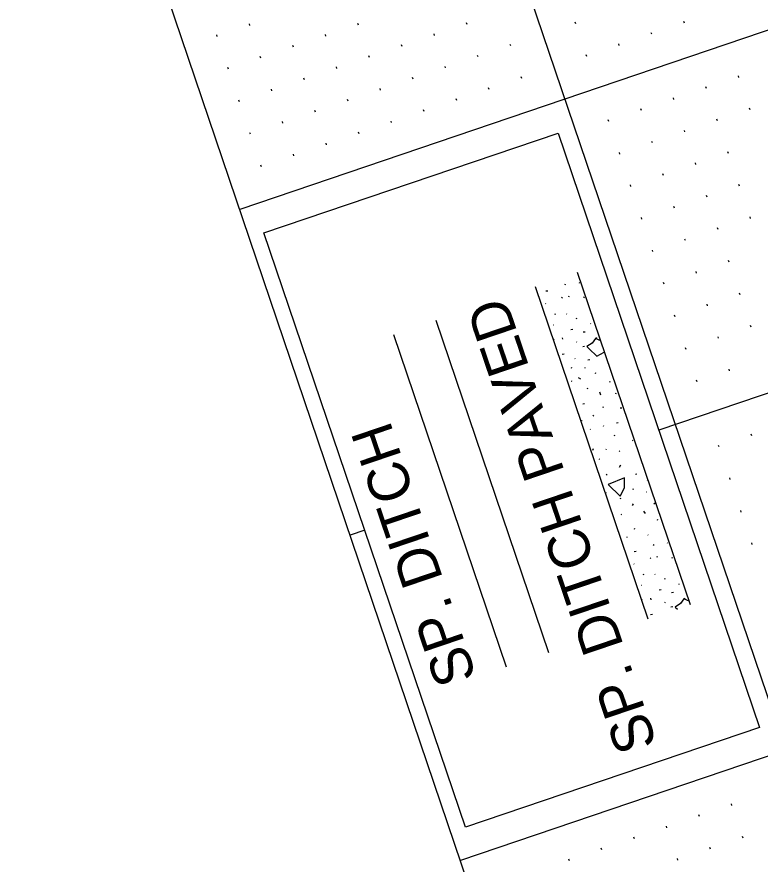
# Model space of a CAD drawing. Extents: x 2150318 to 2152065, y 143281 to 145371.
# Drawn here: x 2150992.2 to 2151100.4, y 144672.2 to 144795.4 of the extents above; entities that cross this region are included whole.
import ezdxf

# ---------------------------------------------------------------- set-up
doc = ezdxf.new("R2010")
doc.units = 0
for name, color, linetype in [('PR_Grading_Txt', 7, 'Continuous'), ('PR_Misc_Improvement', 7, 'Continuous'), ('PR_Storm_Ditch_Paved', 7, 'Continuous'), ('PR_Storm_Ditch_Special', 7, 'Continuous'), ('SHT_Profile_Grid_Major', 7, 'Continuous'), ('SHT_Profile_Grid_Minor', 7, 'Continuous'), ('SHT_Sheet_Border', 7, 'Continuous')]:
    doc.layers.add(name, color=color, linetype=linetype)

msp = doc.modelspace()

# ---------------------------------------------------------------- linework, layer by layer
at = {"layer": 'PR_Misc_Improvement'}
msp.add_lwpolyline([(2151057.47, 144677.53), (2151028.14, 144763.99), (2151070.97, 144778.52), (2151100.3, 144692.06)], close=True, dxfattribs=at)
at = {"layer": 'PR_Storm_Ditch_Paved'}
for p, q in [((2151072.08, 144756.42), (2151071.94, 144756.49)), ((2151073.99, 144756.77), (2151074.06, 144756.74)), ((2151069.2, 144755.55), (2151069.47, 144755.59)), ((2151071.52, 144754.49), (2151071.59, 144754.63)), ((2151072.61, 144754.69), (2151072.47, 144754.76)), ((2151074.79, 144754.56), (2151074.65, 144754.63)), ((2151069.12, 144753.73), (2151069.19, 144753.7)), ((2151070.65, 144752.12), (2151070.51, 144752.18)), ((2151072.18, 144752.23), (2151072.24, 144752.2)), ((2151073.75, 144751.49), (2151073.61, 144751.56)), ((2151075.7, 144752.56), (2151075.74, 144752.56)), ((2151070.23, 144750.64), (2151070.3, 144750.61)), ((2151075.66, 144750.81), (2151075.73, 144750.78)), ((2151072.83, 144749.97), (2151073.1, 144750)), ((2151074.63, 144749.59), (2151074.9, 144749.63)), ((2151070.4, 144748.45), (2151070.26, 144748.52)), ((2151071.64, 144748.52), (2151071.62, 144748.75)), ((2151073.62, 144748.15), (2151073.69, 144748.12)), ((2151076.52, 144748.62), (2151076.59, 144748.76)), ((2151074.54, 144747.48), (2151074.81, 144747.52)), ((2151071.57, 144746.36), (2151071.84, 144746.4)), ((2151073.4, 144745.72), (2151073.47, 144745.68)), ((2151075.31, 144745.55), (2151075.58, 144745.59)), ((2151073.01, 144744.31), (2151072.87, 144744.38)), ((2151074.83, 144744.41), (2151074.9, 144744.37)), ((2151073.87, 144742.98), (2151074.23, 144742.76)), ((2151076.51, 144743.53), (2151076.37, 144743.6)), ((2151072.88, 144742.48), (2151072.95, 144742.44)), ((2151078.49, 144742.3), (2151078.56, 144742.44)), ((2151075.24, 144741.31), (2151075.31, 144741.45)), ((2151077.01, 144740.87), (2151077.15, 144740.46)), ((2151079.37, 144740.57), (2151079.43, 144740.71)), ((2151074.54, 144739.11), (2151074.8, 144739.2)), ((2151077.61, 144738.59), (2151077.47, 144738.66)), ((2151080.15, 144738.41), (2151080.14, 144738.64)), ((2151074.4, 144736.64), (2151074.47, 144736.78)), ((2151076.18, 144737.35), (2151076.04, 144737.42)), ((2151077.55, 144735.86), (2151077.62, 144736)), ((2151079.46, 144736.38), (2151079.73, 144736.42)), ((2151075.62, 144735.43), (2151075.69, 144735.4)), ((2151079.17, 144734.5), (2151079.24, 144734.64)), ((2151081.91, 144733.75), (2151081.77, 144733.82)), ((2151076.02, 144732.39), (2151076.1, 144732.65)), ((2151077.94, 144732.5), (2151077.99, 144732.57)), ((2151079.95, 144732.22), (2151079.86, 144732.3)), ((2151076.91, 144731.13), (2151076.98, 144731.09)), ((2151080.04, 144730.23), (2151079.87, 144729.88)), ((2151078.11, 144728.76), (2151077.97, 144728.83)), ((2151082.23, 144728.89), (2151082.44, 144728.96)), ((2151083.98, 144727.98), (2151084.04, 144728.09)), ((2151077.9, 144726.15), (2151077.97, 144726.29)), ((2151082, 144726.67), (2151081.86, 144726.74)), ((2151083.79, 144726.35), (2151083.85, 144726.32)), ((2151080.03, 144725.31), (2151080.1, 144725.45)), ((2151081.8, 144724.35), (2151081.96, 144724.58)), ((2151084.9, 144724.59), (2151085.09, 144724.72)), ((2151083.7, 144723.2), (2151083.42, 144723.51)), ((2151080.1, 144723.08), (2151080.17, 144723.05)), ((2151085.54, 144722.21), (2151085.4, 144722.28)), ((2151082.17, 144720.89), (2151082.03, 144720.96)), ((2151080.93, 144719.78), (2151081, 144719.75)), ((2151084.01, 144720.07), (2151084.08, 144720.04)), ((2151084.93, 144718.54), (2151084.79, 144718.61)), ((2151086.84, 144718.89), (2151086.91, 144718.86)), ((2151082.05, 144717.67), (2151082.32, 144717.71)), ((2151081.97, 144715.86), (2151082.04, 144715.82)), ((2151084.37, 144716.61), (2151084.44, 144716.75)), ((2151085.46, 144716.81), (2151085.32, 144716.88)), ((2151087.64, 144716.68), (2151087.5, 144716.75)), ((2151088.55, 144714.68), (2151088.59, 144714.68)), ((2151083.5, 144714.24), (2151083.36, 144714.31)), ((2151085.03, 144714.35), (2151085.09, 144714.32)), ((2151086.6, 144713.61), (2151086.46, 144713.68)), ((2151083.08, 144712.76), (2151083.15, 144712.73)), ((2151085.68, 144712.09), (2151085.95, 144712.12)), ((2151088.51, 144712.93), (2151088.58, 144712.9)), ((2151084.49, 144710.64), (2151084.47, 144710.87)), ((2151087.48, 144711.71), (2151087.75, 144711.75)), ((2151089.37, 144710.74), (2151089.44, 144710.88)), ((2151083.25, 144710.57), (2151083.11, 144710.64)), ((2151086.47, 144710.27), (2151086.54, 144710.24)), ((2151087.39, 144709.6), (2151087.66, 144709.64)), ((2151084.42, 144708.48), (2151084.69, 144708.52))]:
    msp.add_line(p, q, dxfattribs=at)
for points in [[(2151077.18, 144748.29), (2151076.43, 144748.65), (2151075.93, 144747.98), (2151075.16, 144747.45), (2151075.5, 144747.12)], [(2151075.5, 144747.12), (2151076.61, 144746.05), (2151077.68, 144746.67), (2151077.7, 144746.77)], [(2151080.61, 144728.37), (2151078.23, 144727.38), (2151080.01, 144725.71), (2151080.63, 144726.89), (2151080.63, 144728.36)], [(2151090.03, 144710.41), (2151089.28, 144710.77), (2151088.78, 144710.1), (2151088.01, 144709.57), (2151088.35, 144709.24)]]:
    msp.add_lwpolyline(points, dxfattribs=at)
at = {"layer": 'PR_Storm_Ditch_Special'}
for p, q in [((2151090.22, 144709.88), (2151073.81, 144758.24)), ((2151084.07, 144707.79), (2151067.66, 144756.16)), ((2151069.62, 144702.89), (2151053.21, 144751.26)), ((2151063.47, 144700.8), (2151047.07, 144749.17))]:
    msp.add_line(p, q, dxfattribs=at)
at = {"layer": 'SHT_Profile_Grid_Major'}
for p, q in [((2151453.47, 143658.9), (2150947.48, 145150.41)), ((2151498.11, 144928.02), (2151024.62, 144767.39)), ((2151514.18, 144880.67), (2151085.63, 144735.29)), ((2151530.24, 144833.32), (2151056.74, 144672.69)), ((2151042.81, 144720.76), (2151040.68, 144720.04))]:
    msp.add_line(p, q, dxfattribs=at)
at = {"layer": 'SHT_Profile_Grid_Minor'}
for p, q in [((2151073.53, 144794.41), (2151073.45, 144794.65)), ((2151089.34, 144794.49), (2151089.26, 144794.73)), ((2151026.1, 144794.16), (2151026.02, 144794.4)), ((2151041.91, 144794.24), (2151041.83, 144794.48)), ((2151057.72, 144794.33), (2151057.64, 144794.56)), ((2151021.36, 144792.55), (2151021.28, 144792.79)), ((2151037.17, 144792.64), (2151037.09, 144792.87)), ((2151052.98, 144792.72), (2151052.9, 144792.96)), ((2151084.61, 144792.89), (2151084.53, 144793.12)), ((2151032.44, 144791.03), (2151032.36, 144791.27)), ((2151048.25, 144791.11), (2151048.17, 144791.35)), ((2151064.06, 144791.2), (2151063.98, 144791.43)), ((2151079.87, 144791.28), (2151079.79, 144791.52)), ((2151043.51, 144789.51), (2151043.43, 144789.74)), ((2151059.33, 144789.59), (2151059.25, 144789.83)), ((2151075.14, 144789.68), (2151075.06, 144789.91)), ((2151027.7, 144789.42), (2151027.62, 144789.66)), ((2151022.97, 144787.82), (2151022.89, 144788.05)), ((2151038.78, 144787.9), (2151038.7, 144788.14)), ((2151054.59, 144787.99), (2151054.51, 144788.22)), ((2151034.04, 144786.29), (2151033.96, 144786.53)), ((2151049.86, 144786.38), (2151049.78, 144786.62)), ((2151065.67, 144786.46), (2151065.59, 144786.7)), ((2151097.29, 144786.63), (2151097.21, 144786.87)), ((2151029.31, 144784.69), (2151029.23, 144784.93)), ((2151045.12, 144784.77), (2151045.04, 144785.01)), ((2151060.93, 144784.86), (2151060.85, 144785.09)), ((2151092.55, 144785.02), (2151092.47, 144785.26)), ((2151087.82, 144783.42), (2151087.74, 144783.65)), ((2151024.57, 144783.08), (2151024.49, 144783.32)), ((2151040.39, 144783.17), (2151040.31, 144783.4)), ((2151056.2, 144783.25), (2151056.12, 144783.49)), ((2151035.65, 144781.56), (2151035.57, 144781.8)), ((2151051.46, 144781.64), (2151051.38, 144781.88)), ((2151083.08, 144781.81), (2151083, 144782.05)), ((2151098.9, 144781.9), (2151098.82, 144782.13)), ((2151030.92, 144779.95), (2151030.84, 144780.19)), ((2151046.73, 144780.04), (2151046.65, 144780.27)), ((2151078.35, 144780.21), (2151078.27, 144780.44)), ((2151094.16, 144780.29), (2151094.08, 144780.53)), ((2151041.99, 144778.43), (2151041.91, 144778.67)), ((2151089.43, 144778.68), (2151089.35, 144778.92)), ((2151026.18, 144778.35), (2151026.1, 144778.58)), ((2151037.26, 144776.82), (2151037.18, 144777.06)), ((2151084.69, 144777.08), (2151084.61, 144777.31)), ((2151032.52, 144775.22), (2151032.44, 144775.46)), ((2151079.96, 144775.47), (2151079.88, 144775.71)), ((2151095.77, 144775.55), (2151095.69, 144775.79)), ((2151027.79, 144773.61), (2151027.71, 144773.85)), ((2151091.03, 144773.95), (2151090.95, 144774.18)), ((2151086.3, 144772.34), (2151086.22, 144772.58)), ((2151081.56, 144770.74), (2151081.48, 144770.97)), ((2151097.37, 144770.82), (2151097.29, 144771.06)), ((2151092.64, 144769.21), (2151092.56, 144769.45)), ((2151087.9, 144767.61), (2151087.82, 144767.84)), ((2151098.98, 144766.08), (2151098.9, 144766.32)), ((2151083.17, 144766), (2151083.09, 144766.24)), ((2151094.24, 144764.48), (2151094.16, 144764.72)), ((2151089.51, 144762.87), (2151089.43, 144763.11)), ((2151084.77, 144761.27), (2151084.69, 144761.5)), ((2151095.85, 144759.74), (2151095.77, 144759.98)), ((2151091.12, 144758.14), (2151091.04, 144758.37)), ((2151086.38, 144756.53), (2151086.3, 144756.77)), ((2151097.46, 144755.01), (2151097.38, 144755.25)), ((2151092.72, 144753.4), (2151092.64, 144753.64)), ((2151087.99, 144751.8), (2151087.91, 144752.03)), ((2151099.06, 144750.27), (2151098.98, 144750.51)), ((2151094.33, 144748.67), (2151094.25, 144748.9)), ((2151089.59, 144747.06), (2151089.51, 144747.3)), ((2151095.93, 144743.93), (2151095.85, 144744.17)), ((2151091.2, 144742.33), (2151091.12, 144742.56)), ((2151099.15, 144734.46), (2151099.07, 144734.7)), ((2151094.41, 144732.86), (2151094.33, 144733.09)), ((2151096.02, 144728.12), (2151095.94, 144728.36)), ((2151097.63, 144723.39), (2151097.55, 144723.62)), ((2151099.23, 144718.65), (2151099.15, 144718.89)), ((2151096.27, 144680.69), (2151096.19, 144680.92)), ((2151091.54, 144679.08), (2151091.46, 144679.32)), ((2151086.8, 144677.47), (2151086.72, 144677.71)), ((2151082.07, 144675.87), (2151081.99, 144676.11)), ((2151097.88, 144675.95), (2151097.8, 144676.19)), ((2151077.33, 144674.26), (2151077.25, 144674.5)), ((2151093.14, 144674.35), (2151093.06, 144674.58)), ((2151072.6, 144672.66), (2151072.52, 144672.89)), ((2151088.41, 144672.74), (2151088.33, 144672.98))]:
    msp.add_line(p, q, dxfattribs=at)
at = {"layer": 'SHT_Sheet_Border'}
msp.add_line((2151406.12, 143642.84), (2150900.13, 145134.35), dxfattribs=at)

# ---------------------------------------------------------------- texts
at = {"layer": 'PR_Grading_Txt'}
for s, p in [('SP. DITCH PAVED', (2151085.42, 144689.56)), ('SP. DITCH', (2151059.14, 144699.32))]:
    msp.add_text(s, height=6, rotation=108.7393, dxfattribs=at).set_placement(p)

doc.saveas('drawing.dxf')
